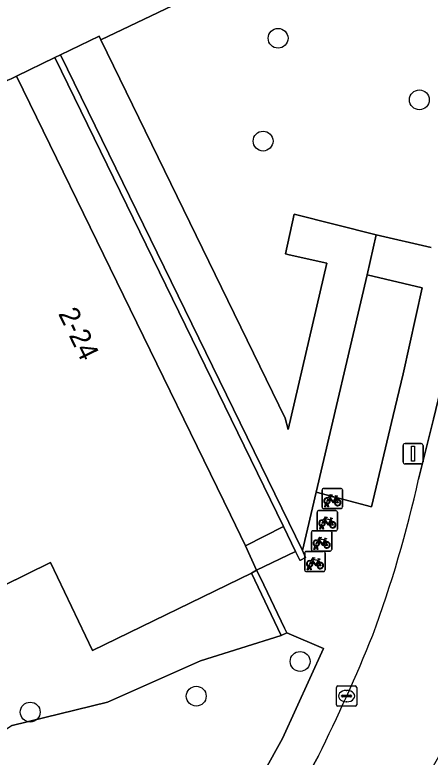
# Model space of a CAD drawing. Extents: x 159039 to 160102, y 381214 to 382524.
# Drawn here: x 159189.02 to 159209.5, y 381558.2 to 381594.79 of the extents above; entities that cross this region are included whole.
import ezdxf

# ---------------------------------------------------------------- set-up
doc = ezdxf.new("R2010")
doc.units = 0
for name, color, linetype in [('IMGEO_Boom', 7, 'Continuous'), ('IMGEO_Fietsenrek', 7, 'Continuous'), ('IMGEO_Groenvoorziening', 7, 'Continuous'), ('IMGEO_Kolk', 7, 'Continuous'), ('IMGEO_Lichtmast', 7, 'Continuous'), ('IMGEO_Muur', 7, 'Continuous'), ('IMGEO_Pand', 7, 'Continuous'), ('IMGEO_Pand_nummerreeks', 7, 'Continuous'), ('IMGEO_Parkeervlak_open', 7, 'Continuous'), ('IMGEO_Rijbaan_lokaal_open', 7, 'Continuous'), ('IMGEO_Voetpad_gesloten', 7, 'Continuous'), ('IMGEO_Voetpad_op_trap', 7, 'Continuous'), ('IMGEO_Voetpad_open', 7, 'Continuous')]:
    doc.layers.add(name, color=color, linetype=linetype)

msp = doc.modelspace()

# ---------------------------------------------------------------- linework, layer by layer
at = {"layer": 'IMGEO_Boom'}
for centre in [(159201.999, 381593.64), (159208.963, 381590.605), (159201.26, 381588.571), (159203.085, 381562.921), (159197.964, 381561.209), (159189.779, 381560.424)]:
    msp.add_circle(centre, 0.489, dxfattribs=at)
at = {"layer": 'IMGEO_Fietsenrek'}
for p, q in [((159204.17, 381570.528), (159204.17, 381571.369)), ((159204.17, 381571.369), (159204.17, 381570.528)), ((159204.245, 381571.453), (159205.086, 381571.453)), ((159205.086, 381571.453), (159204.245, 381571.453)), ((159205.17, 381571.378), (159205.17, 381570.537)), ((159205.17, 381570.537), (159205.17, 381571.378)), ((159204.857, 381571.002), (159204.893, 381570.907)), ((159204.297, 381570.537), (159204.336, 381570.697)), ((159204.366, 381570.685), (159204.331, 381570.537)), ((159204.408, 381570.709), (159204.407, 381570.713)), ((159204.449, 381570.537), (159204.415, 381570.679)), ((159204.439, 381570.72), (159204.44, 381570.713)), ((159204.447, 381570.683), (159204.482, 381570.537)), ((159203.922, 381569.43), (159203.922, 381570.271)), ((159203.922, 381570.271), (159203.922, 381569.43)), ((159203.997, 381570.355), (159204.838, 381570.355)), ((159204.838, 381570.355), (159203.997, 381570.355)), ((159205.095, 381570.453), (159204.254, 381570.453)), ((159204.254, 381570.453), (159205.095, 381570.453)), ((159204.331, 381570.537), (159204.297, 381570.537)), ((159204.482, 381570.537), (159204.449, 381570.537)), ((159204.922, 381570.28), (159204.922, 381569.439)), ((159204.922, 381569.439), (159204.922, 381570.28)), ((159204.609, 381569.904), (159204.645, 381569.809)), ((159204.049, 381569.439), (159204.088, 381569.599)), ((159204.118, 381569.587), (159204.083, 381569.439)), ((159204.16, 381569.611), (159204.159, 381569.615)), ((159204.201, 381569.439), (159204.167, 381569.581)), ((159204.191, 381569.622), (159204.192, 381569.615)), ((159204.199, 381569.585), (159204.234, 381569.439)), ((159203.642, 381568.437), (159203.642, 381569.278)), ((159203.642, 381569.278), (159203.642, 381568.437)), ((159203.717, 381569.362), (159204.558, 381569.362)), ((159204.558, 381569.362), (159203.717, 381569.362)), ((159204.847, 381569.355), (159204.006, 381569.355)), ((159204.006, 381569.355), (159204.847, 381569.355)), ((159204.083, 381569.439), (159204.049, 381569.439)), ((159204.234, 381569.439), (159204.201, 381569.439)), ((159204.642, 381569.287), (159204.642, 381568.446)), ((159204.642, 381568.446), (159204.642, 381569.287)), ((159204.329, 381568.911), (159204.365, 381568.816)), ((159203.769, 381568.446), (159203.808, 381568.606)), ((159203.803, 381568.446), (159203.769, 381568.446)), ((159203.838, 381568.594), (159203.803, 381568.446)), ((159203.88, 381568.618), (159203.879, 381568.622)), ((159203.921, 381568.446), (159203.887, 381568.588)), ((159203.911, 381568.629), (159203.912, 381568.622)), ((159203.919, 381568.592), (159203.954, 381568.446)), ((159203.954, 381568.446), (159203.921, 381568.446)), ((159203.313, 381567.423), (159203.313, 381568.264)), ((159203.313, 381568.264), (159203.313, 381567.423)), ((159203.388, 381568.348), (159204.229, 381568.348)), ((159204.229, 381568.348), (159203.388, 381568.348)), ((159204.567, 381568.362), (159203.726, 381568.362)), ((159203.726, 381568.362), (159204.567, 381568.362)), ((159204.313, 381568.273), (159204.313, 381567.432)), ((159204.313, 381567.432), (159204.313, 381568.273)), ((159204, 381567.897), (159204.036, 381567.802)), ((159204.238, 381567.348), (159203.397, 381567.348)), ((159203.397, 381567.348), (159204.238, 381567.348)), ((159203.44, 381567.432), (159203.479, 381567.592)), ((159203.474, 381567.432), (159203.44, 381567.432)), ((159203.509, 381567.58), (159203.474, 381567.432)), ((159203.551, 381567.604), (159203.55, 381567.608)), ((159203.592, 381567.432), (159203.558, 381567.574)), ((159203.582, 381567.615), (159203.583, 381567.608)), ((159203.59, 381567.578), (159203.625, 381567.432)), ((159203.625, 381567.432), (159203.592, 381567.432))]:
    msp.add_line(p, q, dxfattribs=at)
for points in [[(159204.483, 381570.979), (159204.578, 381571.143), (159204.664, 381571.129), (159204.666, 381571.12), (159204.61, 381571.109), (159204.583, 381571.064), (159204.839, 381571.023)], [(159204.779, 381570.735), (159204.729, 381570.735), (159204.538, 381570.986), (159204.519, 381570.954)], [(159204.826, 381570.998), (159204.569, 381571.039), (159204.552, 381571.01), (159204.719, 381570.79), (159204.826, 381570.998)], [(159204.874, 381570.9), (159204.844, 381570.977), (159204.735, 381570.759), (159204.778, 381570.759)], [(159204.839, 381571.023), (159204.864, 381571.072), (159204.858, 381571.076), (159204.835, 381571.08), (159204.823, 381571.087), (159204.822, 381571.09), (159204.824, 381571.095), (159204.919, 381571.08), (159204.921, 381571.07), (159204.911, 381571.057), (159204.899, 381571.051), (159204.885, 381571.057), (159204.857, 381571.002)], [(159204.504, 381570.927), (159204.452, 381570.837), (159204.412, 381570.812), (159204.413, 381570.859), (159204.468, 381570.953)], [(159204.808, 381570.759), (159204.928, 381570.758), (159204.884, 381570.872)], [(159204.904, 381570.879), (159204.959, 381570.734), (159204.809, 381570.734)], [(159204.235, 381569.881), (159204.33, 381570.045), (159204.416, 381570.031), (159204.418, 381570.022), (159204.362, 381570.011), (159204.335, 381569.966), (159204.591, 381569.925)], [(159204.531, 381569.637), (159204.481, 381569.637), (159204.29, 381569.888), (159204.271, 381569.856)], [(159204.578, 381569.9), (159204.321, 381569.941), (159204.304, 381569.912), (159204.471, 381569.692), (159204.578, 381569.9)], [(159204.626, 381569.802), (159204.596, 381569.879), (159204.487, 381569.661), (159204.53, 381569.661)], [(159204.591, 381569.925), (159204.616, 381569.974), (159204.61, 381569.978), (159204.587, 381569.982), (159204.575, 381569.989), (159204.574, 381569.992), (159204.576, 381569.997), (159204.671, 381569.982), (159204.673, 381569.972), (159204.663, 381569.959), (159204.651, 381569.953), (159204.637, 381569.959), (159204.609, 381569.904)], [(159204.256, 381569.829), (159204.204, 381569.739), (159204.164, 381569.714), (159204.165, 381569.761), (159204.22, 381569.855)], [(159204.56, 381569.661), (159204.68, 381569.66), (159204.636, 381569.774)], [(159204.656, 381569.781), (159204.711, 381569.636), (159204.561, 381569.636)], [(159203.976, 381568.836), (159203.924, 381568.746), (159203.884, 381568.721), (159203.885, 381568.768), (159203.94, 381568.862)], [(159203.955, 381568.888), (159204.05, 381569.052), (159204.136, 381569.038), (159204.138, 381569.029), (159204.082, 381569.018), (159204.055, 381568.973), (159204.311, 381568.932)], [(159204.251, 381568.644), (159204.201, 381568.644), (159204.01, 381568.895), (159203.991, 381568.863)], [(159204.298, 381568.907), (159204.041, 381568.948), (159204.024, 381568.919), (159204.191, 381568.699), (159204.298, 381568.907)], [(159204.346, 381568.809), (159204.316, 381568.886), (159204.207, 381568.668), (159204.25, 381568.668)], [(159204.28, 381568.668), (159204.4, 381568.667), (159204.356, 381568.781)], [(159204.376, 381568.788), (159204.431, 381568.643), (159204.281, 381568.643)], [(159204.311, 381568.932), (159204.336, 381568.981), (159204.33, 381568.985), (159204.307, 381568.989), (159204.295, 381568.996), (159204.294, 381568.999), (159204.296, 381569.004), (159204.391, 381568.989), (159204.393, 381568.979), (159204.383, 381568.966), (159204.371, 381568.96), (159204.357, 381568.966), (159204.329, 381568.911)], [(159203.626, 381567.874), (159203.721, 381568.038), (159203.807, 381568.024), (159203.809, 381568.015), (159203.753, 381568.004), (159203.726, 381567.959), (159203.982, 381567.918)], [(159203.647, 381567.822), (159203.595, 381567.732), (159203.555, 381567.707), (159203.556, 381567.754), (159203.611, 381567.848)], [(159203.922, 381567.63), (159203.872, 381567.63), (159203.681, 381567.881), (159203.662, 381567.849)], [(159203.969, 381567.893), (159203.712, 381567.934), (159203.695, 381567.905), (159203.862, 381567.685), (159203.969, 381567.893)], [(159204.017, 381567.795), (159203.987, 381567.872), (159203.878, 381567.654), (159203.921, 381567.654)], [(159203.951, 381567.654), (159204.071, 381567.653), (159204.027, 381567.767)], [(159204.047, 381567.774), (159204.102, 381567.629), (159203.952, 381567.629)], [(159203.982, 381567.918), (159204.007, 381567.967), (159204.001, 381567.971), (159203.978, 381567.975), (159203.966, 381567.982), (159203.965, 381567.985), (159203.967, 381567.99), (159204.062, 381567.975), (159204.064, 381567.965), (159204.054, 381567.952), (159204.042, 381567.946), (159204.028, 381567.952), (159204, 381567.897)]]:
    msp.add_lwpolyline(points, dxfattribs=at)
for centre, radius, start, end in [((159204.248, 381571.375), 0.0779, 92.4484, 184.2845), ((159204.248, 381571.375), 0.0779, 92.4484, 184.2845), ((159205.092, 381571.375), 0.0779, 2.4484, 94.2845), ((159205.092, 381571.375), 0.0779, 2.4484, 94.2845), ((159204.41, 381570.838), 0.159, 62.6766, 242.1369), ((159204.41, 381570.838), 0.129, 63.3192, 238.903), ((159204.39, 381570.709), 0.0499, 12.8025, 158.6934), ((159204.41, 381570.838), 0.159, 253.9967, 271.7867), ((159204.39, 381570.709), 0.0174, 12.8025, 163.4502), ((159204.41, 381570.838), 0.129, 253.415, 269.0204), ((159204.41, 381570.838), 0.129, 283.6043, 43.4302), ((159204.41, 381570.838), 0.159, 283.5766, 46.6042), ((159204.937, 381570.754), 0.159, 113.3408, 178.3217), ((159204.937, 381570.754), 0.159, 187.0065, 105.7708), ((159204.937, 381570.754), 0.129, 113.923, 177.9556), ((159204.937, 381570.754), 0.129, 188.6715, 104.5883), ((159204, 381570.277), 0.0779, 92.4484, 184.2845), ((159204, 381570.277), 0.0779, 92.4484, 184.2845), ((159204.248, 381570.531), 0.0779, 182.4484, 274.2845), ((159204.248, 381570.531), 0.0779, 182.4484, 274.2845), ((159204.844, 381570.277), 0.0779, 2.4484, 94.2845), ((159204.844, 381570.277), 0.0779, 2.4484, 94.2845), ((159205.092, 381570.531), 0.0779, 272.4484, 4.2845), ((159205.092, 381570.531), 0.0779, 272.4484, 4.2845), ((159204.162, 381569.74), 0.159, 62.6766, 242.1369), ((159204.162, 381569.74), 0.129, 63.3192, 238.903), ((159204.142, 381569.611), 0.0499, 12.8025, 158.6934), ((159204.162, 381569.74), 0.159, 253.9967, 271.7867), ((159204.142, 381569.611), 0.0174, 12.8025, 163.4502), ((159204.162, 381569.74), 0.129, 253.415, 269.0204), ((159204.162, 381569.74), 0.129, 283.6043, 43.4302), ((159204.162, 381569.74), 0.159, 283.5766, 46.6042), ((159204.689, 381569.656), 0.159, 113.3408, 178.3217), ((159204.689, 381569.656), 0.159, 187.0065, 105.7708), ((159204.689, 381569.656), 0.129, 113.923, 177.9556), ((159204.689, 381569.656), 0.129, 188.6715, 104.5883), ((159203.72, 381569.284), 0.0779, 92.4484, 184.2845), ((159203.72, 381569.284), 0.0779, 92.4484, 184.2845), ((159204, 381569.433), 0.0779, 182.4484, 274.2845), ((159204, 381569.433), 0.0779, 182.4484, 274.2845), ((159204.564, 381569.284), 0.0779, 2.4484, 94.2845), ((159204.564, 381569.284), 0.0779, 2.4484, 94.2845), ((159204.844, 381569.433), 0.0779, 272.4484, 4.2845), ((159204.844, 381569.433), 0.0779, 272.4484, 4.2845), ((159203.882, 381568.747), 0.159, 62.6766, 242.1369), ((159203.882, 381568.747), 0.129, 63.3192, 238.903), ((159203.882, 381568.747), 0.129, 283.6043, 43.4302), ((159203.882, 381568.747), 0.159, 283.5766, 46.6042), ((159204.409, 381568.663), 0.159, 113.3408, 178.3217), ((159204.409, 381568.663), 0.159, 187.0065, 105.7708), ((159204.409, 381568.663), 0.129, 113.923, 177.9556), ((159204.409, 381568.663), 0.129, 188.6715, 104.5883), ((159203.72, 381568.44), 0.0779, 182.4484, 274.2845), ((159203.72, 381568.44), 0.0779, 182.4484, 274.2845), ((159203.862, 381568.618), 0.0499, 12.8025, 158.6934), ((159203.882, 381568.747), 0.159, 253.9967, 271.7867), ((159203.862, 381568.618), 0.0174, 12.8025, 163.4502), ((159203.882, 381568.747), 0.129, 253.415, 269.0204), ((159204.564, 381568.44), 0.0779, 272.4484, 4.2845), ((159204.564, 381568.44), 0.0779, 272.4484, 4.2845), ((159203.391, 381568.27), 0.0779, 92.4484, 184.2845), ((159203.391, 381568.27), 0.0779, 92.4484, 184.2845), ((159204.235, 381568.27), 0.0779, 2.4484, 94.2845), ((159204.235, 381568.27), 0.0779, 2.4484, 94.2845), ((159203.553, 381567.733), 0.159, 62.6766, 242.1369), ((159203.553, 381567.733), 0.129, 63.3192, 238.903), ((159203.553, 381567.733), 0.129, 283.6043, 43.4302), ((159203.553, 381567.733), 0.159, 283.5766, 46.6042), ((159204.08, 381567.649), 0.159, 113.3408, 178.3217), ((159204.08, 381567.649), 0.159, 187.0065, 105.7708), ((159204.08, 381567.649), 0.129, 113.923, 177.9556), ((159204.08, 381567.649), 0.129, 188.6715, 104.5883), ((159203.391, 381567.426), 0.0779, 182.4484, 274.2845), ((159203.391, 381567.426), 0.0779, 182.4484, 274.2845), ((159203.533, 381567.604), 0.0499, 12.8025, 158.6934), ((159203.553, 381567.733), 0.159, 253.9967, 271.7867), ((159203.533, 381567.604), 0.0174, 12.8025, 163.4502), ((159203.553, 381567.733), 0.129, 253.415, 269.0204), ((159204.235, 381567.426), 0.0779, 272.4484, 4.2845), ((159204.235, 381567.426), 0.0779, 272.4484, 4.2845)]:
    msp.add_arc(centre, radius, start, end, dxfattribs=at)
at = {"layer": 'IMGEO_Groenvoorziening'}
for points in [[(159215.61, 381599.061), (159217.597, 381602.497), (159214.846, 381603.954), (159198.911, 381596.28), (159193.268, 381593.562), (159202.354, 381574.906), (159202.503, 381574.358), (159204.406, 381582.55), (159202.55, 381582.967), (159202.367, 381583.018), (159202.788, 381584.972), (159206.836, 381583.949), (159209.539, 381583.329)], [(159197.939, 381551.409), (159202.211, 381559.115), (159204.23, 381563.566), (159202.427, 381564.333), (159202.157, 381564.208), (159198.172, 381562.945), (159193.584, 381560.916), (159188.887, 381559.765), (159187.166, 381558.623), (159180.427, 381562.914), (159174.236, 381567.092), (159167.702, 381571.776), (159165.31, 381578.321), (159169.027, 381580.869), (159166.457, 381589.154), (159164.643, 381596.98)], [(159188.887, 381559.765), (159193.584, 381560.916), (159198.172, 381562.945), (159202.157, 381564.208), (159200.691, 381567.278), (159192.85, 381563.462), (159190.778, 381567.798), (159187.29, 381566.088)]]:
    msp.add_lwpolyline(points, dxfattribs=at)
msp.add_lwpolyline([(159207.664, 381575.044), (159208.162, 381577.105), (159209.094, 381581.331), (159206.389, 381581.973), (159203.881, 381571.269), (159206.596, 381570.536)], close=True, dxfattribs=at)
at = {"layer": 'IMGEO_Kolk'}
for p, q in [((159204.874, 381560.788), (159204.874, 381561.64)), ((159204.949, 381561.714), (159205.801, 381561.714)), ((159205.362, 381561.494), (159205.387, 381561.494)), ((159205.875, 381561.64), (159205.875, 381560.788)), ((159205.133, 381561.208), (159205.133, 381561.22)), ((159205.571, 381561.171), (159205.173, 381561.171)), ((159205.176, 381561.257), (159205.574, 381561.257)), ((159205.617, 381561.22), (159205.617, 381561.208)), ((159205.801, 381560.714), (159204.949, 381560.714)), ((159205.385, 381560.934), (159205.36, 381560.934))]:
    msp.add_line(p, q, dxfattribs=at)
for points in [[(159204.874, 381560.788), (159204.874, 381561.64)], [(159204.949, 381561.714), (159205.801, 381561.714)], [(159205.875, 381561.64), (159205.875, 381560.788)], [(159205.801, 381560.714), (159204.949, 381560.714)]]:
    msp.add_lwpolyline(points, dxfattribs=at)
for centre, radius, start, end in [((159204.951, 381561.638), 0.0765, 91.552, 178.448), ((159204.951, 381561.638), 0.0765, 91.552, 178.448), ((159205.799, 381561.638), 0.0765, 1.552, 88.448), ((159205.799, 381561.638), 0.0765, 1.552, 88.448), ((159205.173, 381561.217), 0.0403, 85.8775, 175.7526), ((159205.17, 381561.207), 0.0366, 178.938, 274.7102), ((159205.574, 381561.214), 0.043, 264.8664, 352.4533), ((159205.578, 381561.219), 0.0386, 1.7309, 96.639), ((159204.951, 381560.79), 0.0765, 181.552, 268.448), ((159204.951, 381560.79), 0.0765, 181.552, 268.448), ((159205.799, 381560.79), 0.0765, 271.552, 358.448), ((159205.799, 381560.79), 0.0765, 271.552, 358.448)]:
    msp.add_arc(centre, radius, start, end, dxfattribs=at)
for centre, major_axis, ratio, start_param, end_param in [((159205.361, 381561.214), (-0.387, 0.002), 0.722429, 4.712389, 7.853982), ((159205.386, 381561.214), (-0.39, 0.002), 0.717154, 1.570796, 4.712389)]:
    msp.add_ellipse(centre, major_axis=major_axis, ratio=ratio, start_param=start_param, end_param=end_param, dxfattribs=at)
at = {"layer": 'IMGEO_Lichtmast'}
for p, q in [((159208.157, 381572.761), (159208.157, 381573.561)), ((159208.157, 381573.561), (159208.157, 381572.761)), ((159208.257, 381573.661), (159209.047, 381573.661)), ((159209.047, 381573.661), (159208.257, 381573.661)), ((159209.147, 381573.561), (159209.147, 381572.761)), ((159209.147, 381572.761), (159209.147, 381573.561)), ((159209.047, 381572.661), (159208.257, 381572.661)), ((159208.257, 381572.661), (159209.047, 381572.661))]:
    msp.add_line(p, q, dxfattribs=at)
msp.add_lwpolyline([(159208.577, 381573.536), (159208.727, 381573.536), (159208.727, 381572.786), (159208.577, 381572.786), (159208.577, 381573.536)], dxfattribs=at)
for centre, start, end in [((159208.257, 381573.561), 90, 180), ((159208.257, 381573.561), 90, 180), ((159209.047, 381573.561), 0, 90), ((159209.047, 381573.561), 360, 90), ((159208.257, 381572.761), 180, 270), ((159208.257, 381572.761), 180, 270), ((159209.047, 381572.761), 270, 0), ((159209.047, 381572.761), 270, 0)]:
    msp.add_arc(centre, 0.1, start, end, dxfattribs=at)
at = {"layer": 'IMGEO_Muur'}
for points in [[(159191.267, 381592.823), (159190.988, 381592.684), (159202.264, 381569.577), (159202.865, 381568.336), (159203.072, 381567.908), (159203.097, 381567.92), (159203.358, 381568.043), (159203.208, 381568.394)], [(159201.133, 381567.05), (159200.943, 381567.422), (159200.691, 381567.278), (159202.157, 381564.208), (159202.427, 381564.333), (159202.311, 381564.566)]]:
    msp.add_lwpolyline(points, close=True, dxfattribs=at)
at = {"layer": 'IMGEO_Pand'}
msp.add_lwpolyline([(159200.943, 381567.422), (159200.386, 381568.621), (159199.645, 381570.142), (159189.103, 381591.765), (159188.837, 381591.646), (159188.675, 381591.573), (159187.237, 381590.869), (159176.978, 381585.842), (159177.09, 381585.626), (159186.648, 381566.016), (159186.744, 381565.827), (159187.29, 381566.088), (159190.778, 381567.798), (159192.85, 381563.462), (159200.691, 381567.278)], close=True, dxfattribs=at)
at = {"layer": 'IMGEO_Parkeervlak_open'}
msp.add_lwpolyline([(159186.946, 381595.279), (159185.299, 381594.482), (159175.163, 381589.556), (159176.978, 381585.842), (159187.237, 381590.869), (159188.675, 381591.573), (159188.837, 381591.646), (159189.103, 381591.765), (159190.988, 381592.684), (159191.267, 381592.823), (159193.176, 381593.751), (159193.268, 381593.562), (159198.911, 381596.28)], dxfattribs=at)
at = {"layer": 'IMGEO_Rijbaan_lokaal_open'}
for points in [[(159211.516, 381583.139), (159211.024, 381580.932), (159210.747, 381579.765), (159210.264, 381577.571), (159209.883, 381575.825), (159209.653, 381574.858), (159208.927, 381571.913)], [(159203.987, 381558.272), (159197.281, 381546.224), (159192.572, 381537.926), (159197.222, 381535.339), (159202.327, 381544.533), (159207.32, 381553.722), (159210.549, 381559.319)]]:
    msp.add_lwpolyline(points, dxfattribs=at)
for centre, radius, start, end in [((159148.984, 381585.314), 61.423, 339.90345, 347.39802), ((159123.832, 381598.028), 89.473, 333.61918, 337.79138)]:
    msp.add_arc(centre, radius, start, end, dxfattribs=at)
at = {"layer": 'IMGEO_Voetpad_gesloten'}
for points in [[(159206.836, 381583.949), (159202.788, 381584.972), (159202.367, 381583.018), (159202.55, 381582.967), (159204.406, 381582.55), (159202.503, 381574.358), (159202.354, 381574.906), (159193.268, 381593.562), (159193.176, 381593.751), (159191.267, 381592.823), (159203.208, 381568.394), (159203.881, 381571.269), (159206.389, 381581.973)], [(159190.988, 381592.684), (159189.103, 381591.765), (159199.645, 381570.142), (159200.386, 381568.621), (159202.264, 381569.577)]]:
    msp.add_lwpolyline(points, close=True, dxfattribs=at)
at = {"layer": 'IMGEO_Voetpad_op_trap'}
msp.add_lwpolyline([(159202.264, 381569.577), (159200.386, 381568.621), (159200.943, 381567.422), (159202.865, 381568.336)], close=True, dxfattribs=at)
at = {"layer": 'IMGEO_Voetpad_open'}
for points in [[(159209.539, 381583.329), (159206.836, 381583.949), (159206.389, 381581.973), (159209.094, 381581.331), (159208.162, 381577.105), (159207.664, 381575.044), (159206.596, 381570.536), (159203.881, 381571.269), (159203.208, 381568.394), (159203.358, 381568.043), (159203.097, 381567.92), (159203.072, 381567.908), (159202.865, 381568.336), (159200.943, 381567.422), (159201.133, 381567.05), (159202.311, 381564.566), (159202.427, 381564.333), (159204.23, 381563.566), (159202.211, 381559.115), (159197.939, 381551.409)], [(159208.927, 381571.913), (159209.653, 381574.858), (159209.883, 381575.825), (159210.264, 381577.571), (159210.747, 381579.765), (159211.024, 381580.932), (159211.516, 381583.139)], [(159191.522, 381536.074), (159192.27, 381537.381), (159192.572, 381537.926), (159197.281, 381546.224), (159203.987, 381558.272)]]:
    msp.add_lwpolyline(points, dxfattribs=at)
for centre, radius, start, end in [((159148.984, 381585.314), 61.423, 339.90345, 347.39802), ((159123.832, 381598.028), 89.473, 333.61918, 337.79138)]:
    msp.add_arc(centre, radius, start, end, dxfattribs=at)

# ---------------------------------------------------------------- texts
at = {"layer": 'IMGEO_Pand_nummerreeks'}
msp.add_text('2-24', height=1, rotation=295.9375, dxfattribs=at).set_placement((159191.144, 381580.07))

doc.saveas('drawing.dxf')
